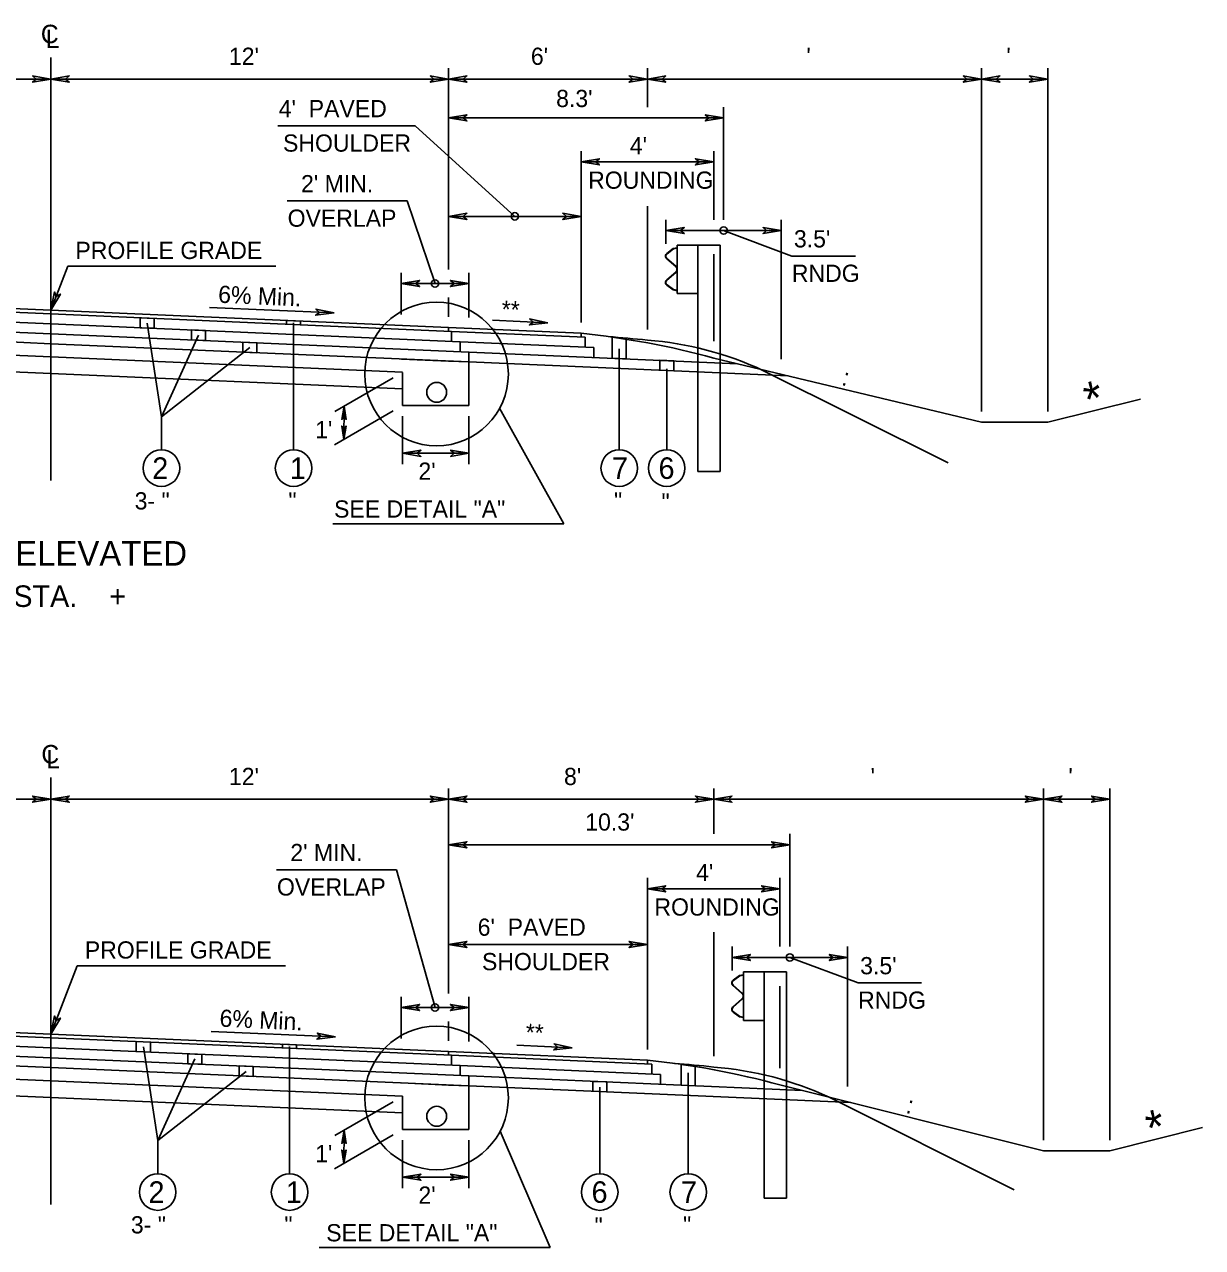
# Model space of a CAD drawing. Extents: x -592 to 1199, y -590 to 416.
# Drawn here: x 1091.9 to 1187.7, y 108.9 to 208.3 of the extents above; entities that cross this region are included whole.
import ezdxf

# ---------------------------------------------------------------- set-up
doc = ezdxf.new("R2010")
doc.units = 0
doc.layers.add('1', color=7, linetype='Continuous')
doc.layers.add('Des_ Drain_ Ftrs', color=7, linetype='Continuous')

msp = doc.modelspace()

# ---------------------------------------------------------------- linework, layer by layer
at = {"layer": '1'}
for p, q in [((1094.032, 171.242), (1094.032, 205.648)), ((1094.032, 203.888), (1061.702, 203.888)), ((1094.032, 203.888), (1126.361, 203.888)), ((1126.361, 188.391), (1126.361, 204.768)), ((1126.361, 203.888), (1142.526, 203.888)), ((1142.526, 201.606), (1142.526, 204.768)), ((1142.526, 203.888), (1169.691, 203.888)), ((1169.691, 176.868), (1169.691, 204.768)), ((1169.691, 203.888), (1175.079, 203.888)), ((1175.079, 176.868), (1175.079, 204.768)), ((1148.721, 192.45), (1148.721, 201.606)), ((1123.632, 200.084), (1112.491, 200.084)), ((1131.749, 192.725), (1123.635, 200.082)), ((1126.36, 200.726), (1148.721, 200.726)), ((1137.137, 184.095), (1137.137, 198.032)), ((1147.914, 192.45), (1147.914, 198.032)), ((1137.137, 197.152), (1147.914, 197.152)), ((1113.242, 193.979), (1123.006, 193.979)), ((1125.26, 187.263), (1123.006, 193.979)), ((1142.526, 183.54), (1142.526, 193.551)), ((1126.361, 192.725), (1137.137, 192.725)), ((1144.029, 190.499), (1144.029, 192.45)), ((1153.413, 181.106), (1153.413, 192.45)), ((1144.029, 191.57), (1153.413, 191.57)), ((1148.721, 191.57), (1154.279, 189.498)), ((1144.627, 190.102), (1144.11, 189.713)), ((1144.639, 190.074), (1144.128, 189.689)), ((1144.942, 190.158), (1144.627, 190.102)), ((1144.942, 190.127), (1144.639, 190.074)), ((1144.942, 190.386), (1144.942, 186.454)), ((1144.942, 190.386), (1146.627, 190.386)), ((1146.627, 190.386), (1146.627, 171.989)), ((1148.452, 190.386), (1146.627, 190.386)), ((1148.452, 190.386), (1148.452, 171.989)), ((1144.095, 189.281), (1144.827, 188.645)), ((1144.114, 189.303), (1144.846, 188.668)), ((1147.914, 182.572), (1147.914, 189.647)), ((1154.279, 189.498), (1159.434, 189.498)), ((1094.032, 185.1), (1095.408, 188.672)), ((1112.327, 188.672), (1095.408, 188.672)), ((1122.517, 184.734), (1122.517, 188.143)), ((1128.003, 184.494), (1128.003, 188.143)), ((1144.827, 188.195), (1144.095, 187.559)), ((1144.846, 188.172), (1144.114, 187.537)), ((1144.913, 188.458), (1144.913, 188.382)), ((1144.942, 188.458), (1144.942, 188.382)), ((1122.517, 187.263), (1128.003, 187.263)), ((1144.11, 187.127), (1144.627, 186.738)), ((1144.128, 187.151), (1144.639, 186.766)), ((1094.032, 184.799), (1061.356, 186.226)), ((1094.032, 185.099), (1061.696, 186.511)), ((1126.361, 184.566), (1126.361, 186.134)), ((1144.627, 186.738), (1144.942, 186.682)), ((1144.639, 186.766), (1144.942, 186.712)), ((1144.942, 186.454), (1146.627, 186.454)), ((1094.032, 183.99), (1060.434, 185.457)), ((1126.366, 183.686), (1094.032, 185.1)), ((1106.935, 185.31), (1117.047, 184.868)), ((1094.032, 183.181), (1059.511, 184.688)), ((1126.601, 183.377), (1094.032, 184.799)), ((1127.304, 182.537), (1094.032, 183.99)), ((1101.851, 184.052), (1103.015, 176.426)), ((1113.759, 184.06), (1113.759, 173.742)), ((1134.427, 184.081), (1129.933, 184.277)), ((1094.032, 182.372), (1059.511, 183.879)), ((1128.008, 181.697), (1094.032, 183.181)), ((1106.027, 183.069), (1103.015, 176.426)), ((1137.137, 183.215), (1126.366, 183.686)), ((1126.366, 183.686), (1126.366, 183.386)), ((1126.601, 183.377), (1126.601, 182.568)), ((1137.471, 182.902), (1126.603, 183.377)), ((1137.137, 183.215), (1137.137, 182.915)), ((1094.032, 181.293), (1064.9, 182.565)), ((1128.008, 180.888), (1094.032, 182.372)), ((1110.202, 182.055), (1103.015, 176.426)), ((1127.304, 182.537), (1127.304, 181.728)), ((1138.166, 182.062), (1127.314, 182.536)), ((1137.471, 182.902), (1137.471, 182.093)), ((1138.166, 182.062), (1138.166, 181.252)), ((1140.235, 181.948), (1140.235, 173.742)), ((1144.029, 182.439), (1144.029, 182.439)), ((1094.032, 179.945), (1064.9, 181.217)), ((1122.619, 180.045), (1094.032, 181.293)), ((1126.361, 180.96), (1122.522, 181.128)), ((1128.008, 180.888), (1126.351, 180.961)), ((1128.008, 181.697), (1128.008, 180.888)), ((1149.853, 180.742), (1128.025, 181.695)), ((1147.914, 181.206), (1169.691, 175.988)), ((1122.619, 177.35), (1122.619, 180.044)), ((1122.619, 180.044), (1122.619, 180.044)), ((1128.008, 177.35), (1128.008, 180.888)), ((1153.971, 179.755), (1128.008, 180.888)), ((1144.095, 180.34), (1144.095, 173.742)), ((1151.914, 180.206), (1166.965, 172.68)), ((1122.619, 178.697), (1094.032, 179.945)), ((1121.857, 179.604), (1117.1, 176.858)), ((1117.862, 177.298), (1117.841, 174.592)), ((1122.619, 177.35), (1128.008, 177.35)), ((1130.513, 177.123), (1135.74, 167.732)), ((1182.615, 177.872), (1175.079, 175.988)), ((1103.015, 176.426), (1103.015, 173.742)), ((1121.857, 176.91), (1117.085, 174.155)), ((1122.619, 176.47), (1122.619, 172.584)), ((1128.008, 176.47), (1128.008, 172.584)), ((1169.691, 175.988), (1175.08, 175.988)), ((1122.619, 173.464), (1128.008, 173.464)), ((1148.452, 171.989), (1146.627, 171.989)), ((1116.954, 167.732), (1135.74, 167.732)), ((1094.032, 112.392), (1094.032, 147.103)), ((1126.361, 129.541), (1126.361, 146.223)), ((1147.914, 142.521), (1147.914, 146.223)), ((1174.737, 117.641), (1174.737, 146.223)), ((1180.125, 117.641), (1180.125, 146.223)), ((1094.032, 145.343), (1061.702, 145.343)), ((1094.032, 145.343), (1126.361, 145.343)), ((1126.361, 145.343), (1147.914, 145.343)), ((1147.914, 145.343), (1174.737, 145.343)), ((1174.737, 145.343), (1180.125, 145.343)), ((1154.109, 133.365), (1154.109, 142.521)), ((1126.359, 141.641), (1154.109, 141.641)), ((1112.373, 139.613), (1122.137, 139.613)), ((1125.26, 128.413), (1122.137, 139.613)), ((1142.526, 125.011), (1142.526, 138.947)), ((1153.302, 133.365), (1153.302, 138.947)), ((1142.526, 138.067), (1153.302, 138.067)), ((1147.914, 124.455), (1147.914, 134.548)), ((1126.361, 133.543), (1142.526, 133.543)), ((1149.417, 131.414), (1149.417, 133.365)), ((1158.801, 122.001), (1158.801, 133.365)), ((1149.417, 132.485), (1158.801, 132.485)), ((1154.109, 132.485), (1159.666, 130.414)), ((1094.032, 126.25), (1096.173, 131.806)), ((1113.091, 131.806), (1096.173, 131.806)), ((1150.33, 131.301), (1150.33, 127.369)), ((1150.33, 131.301), (1152.015, 131.301)), ((1152.015, 131.301), (1152.015, 112.904)), ((1153.84, 131.301), (1152.015, 131.301)), ((1153.84, 131.301), (1153.84, 112.904)), ((1150.015, 131.017), (1149.498, 130.628)), ((1150.027, 130.989), (1149.516, 130.604)), ((1150.33, 131.073), (1150.015, 131.017)), ((1150.33, 131.042), (1150.027, 130.989)), ((1159.666, 130.414), (1164.821, 130.414)), ((1122.517, 125.884), (1122.517, 129.293)), ((1128.003, 125.645), (1128.003, 129.293)), ((1149.483, 130.196), (1150.214, 129.56)), ((1149.502, 130.218), (1150.234, 129.583)), ((1150.3, 129.373), (1150.3, 129.297)), ((1150.33, 129.373), (1150.33, 129.297)), ((1153.302, 123.488), (1153.302, 130.135)), ((1122.517, 128.413), (1128.003, 128.413)), ((1150.214, 129.11), (1149.483, 128.474)), ((1150.234, 129.087), (1149.502, 128.452)), ((1094.032, 125.949), (1061.356, 127.376)), ((1094.032, 126.249), (1061.696, 127.661)), ((1126.361, 125.716), (1126.361, 127.285)), ((1149.498, 128.042), (1150.015, 127.653)), ((1149.516, 128.066), (1150.027, 127.681)), ((1150.015, 127.653), (1150.33, 127.597)), ((1150.027, 127.681), (1150.33, 127.627)), ((1150.33, 127.369), (1152.015, 127.369)), ((1094.032, 125.14), (1060.434, 126.607)), ((1107.047, 126.461), (1117.16, 126.019)), ((1094.032, 124.331), (1059.511, 125.838)), ((1126.366, 124.836), (1094.032, 126.25)), ((1126.601, 124.527), (1094.032, 125.949)), ((1136.41, 125.145), (1131.916, 125.341)), ((1094.032, 123.522), (1059.511, 125.029)), ((1127.304, 123.688), (1094.032, 125.14)), ((1128.008, 122.848), (1094.032, 124.331)), ((1101.546, 125.218), (1102.71, 117.592)), ((1113.432, 125.23), (1113.432, 114.893)), ((1142.526, 124.131), (1126.366, 124.836)), ((1126.366, 124.836), (1126.366, 124.536)), ((1142.888, 123.815), (1126.601, 124.527)), ((1126.601, 124.527), (1126.601, 123.718)), ((1094.032, 122.443), (1064.9, 123.715)), ((1128.008, 122.039), (1094.032, 123.522)), ((1105.722, 124.234), (1102.71, 117.592)), ((1143.583, 122.977), (1127.304, 123.688)), ((1127.304, 123.688), (1127.304, 122.878)), ((1142.526, 124.131), (1142.526, 123.83)), ((1142.888, 123.815), (1142.888, 123.007)), ((1149.417, 123.354), (1149.417, 123.354)), ((1094.032, 121.095), (1064.9, 122.367)), ((1122.619, 121.195), (1094.032, 122.443)), ((1109.897, 123.221), (1102.71, 117.592)), ((1128.008, 122.848), (1128.008, 122.039)), ((1155.135, 121.663), (1128.008, 122.848)), ((1143.583, 122.977), (1143.583, 122.168)), ((1145.846, 123.095), (1145.846, 114.893)), ((1126.361, 122.111), (1122.522, 122.278)), ((1128.008, 122.039), (1126.362, 122.111)), ((1128.008, 118.501), (1128.008, 122.039)), ((1159.055, 120.683), (1128.008, 122.039)), ((1138.65, 121.947), (1138.65, 114.893)), ((1153.302, 122.121), (1174.737, 116.761)), ((1122.619, 119.847), (1094.032, 121.095)), ((1121.857, 120.755), (1117.1, 118.008)), ((1122.619, 118.501), (1122.619, 121.195)), ((1122.619, 121.195), (1122.619, 121.195)), ((1157.301, 121.121), (1172.352, 113.595)), ((1117.862, 118.448), (1117.841, 115.742)), ((1122.619, 118.501), (1128.008, 118.501)), ((1130.561, 118.365), (1134.616, 108.9)), ((1187.66, 118.645), (1180.125, 116.761)), ((1102.71, 117.592), (1102.71, 114.893)), ((1121.857, 118.061), (1117.085, 115.305)), ((1122.619, 117.621), (1122.619, 113.735)), ((1128.008, 117.621), (1128.008, 113.735)), ((1174.737, 116.761), (1180.125, 116.761)), ((1122.619, 114.615), (1128.008, 114.615)), ((1153.84, 112.904), (1152.015, 112.904)), ((1115.83, 108.9), (1134.616, 108.9))]:
    msp.add_line(p, q, dxfattribs=at)
for points in [[(1101.278, 184.483), (1102.425, 184.433), (1102.425, 183.624), (1101.278, 183.674)], [(1113.185, 184.262), (1114.332, 184.212), (1114.332, 183.913), (1113.185, 183.963)], [(1105.454, 183.491), (1106.6, 183.441), (1106.6, 182.632), (1105.454, 182.682)], [(1109.629, 182.5), (1110.776, 182.45), (1110.776, 181.641), (1109.629, 181.691)], [(1139.662, 182.907), (1140.808, 182.735), (1140.808, 181.137), (1139.662, 181.187)], [(1143.526, 181.022), (1144.673, 180.972), (1144.673, 180.165), (1143.526, 180.215)], [(1100.973, 125.646), (1102.12, 125.596), (1102.12, 124.787), (1100.973, 124.837)], [(1112.858, 125.427), (1114.005, 125.377), (1114.005, 125.077), (1112.858, 125.127)], [(1105.149, 124.655), (1106.295, 124.605), (1106.295, 123.796), (1105.149, 123.846)], [(1109.324, 123.663), (1110.471, 123.613), (1110.471, 122.804), (1109.324, 122.854)], [(1145.273, 123.79), (1146.42, 123.614), (1146.42, 122.044), (1145.273, 122.094)], [(1138.077, 122.408), (1139.223, 122.358), (1139.223, 121.549), (1138.077, 121.599)]]:
    msp.add_lwpolyline(points, close=True, dxfattribs=at)
for centre, radius in [((1131.749, 192.725), 0.3), ((1148.722, 191.57), 0.3), ((1125.26, 187.263), 0.3), ((1125.382, 179.908), 5.838), ((1125.394, 178.421), 0.808), ((1103.015, 172.257), 1.485), ((1113.759, 172.257), 1.485), ((1140.235, 172.257), 1.485), ((1144.095, 172.257), 1.485), ((1154.109, 132.485), 0.3), ((1125.26, 128.413), 0.3), ((1125.382, 121.059), 5.838), ((1125.394, 119.571), 0.808), ((1102.71, 113.407), 1.485), ((1113.432, 113.407), 1.485), ((1138.65, 113.407), 1.485), ((1145.846, 113.407), 1.485)]:
    msp.add_circle(centre, radius, dxfattribs=at)
for centre, radius, start, end in [((1144.278, 189.491), 0.278, 126.97989, 229.02099), ((1144.278, 189.491), 0.249, 126.97989, 229.02099), ((1144.664, 188.458), 0.249, 0, 49.03649), ((1144.664, 188.382), 0.249, 310.96352, 0), ((1144.664, 188.458), 0.278, 0, 49.03649), ((1144.664, 188.382), 0.278, 310.96352, 0), ((1144.278, 187.349), 0.278, 130.97902, 233.02011), ((1144.278, 187.349), 0.249, 130.97902, 233.02011), ((1130.253, 116.381), 67.188, 74.76019, 84.11876), ((1131.707, 81.996), 101.244, 83.86333, 85.67746), ((1140.407, 155.374), 27.368, 65.13739, 85.55132), ((1149.665, 130.406), 0.278, 126.97989, 229.02099), ((1149.665, 130.406), 0.249, 126.97989, 229.02099), ((1150.052, 129.373), 0.249, 0, 49.03649), ((1150.052, 129.297), 0.249, 310.96352, 0), ((1150.052, 129.373), 0.278, 0, 49.03649), ((1150.052, 129.297), 0.278, 310.96352, 0), ((1149.665, 128.264), 0.278, 130.97902, 233.02011), ((1149.665, 128.264), 0.249, 130.97902, 233.02011), ((1135.641, 57.296), 67.188, 74.76019, 84.11876), ((1137.094, 22.911), 101.244, 83.86333, 85.67746), ((1145.794, 96.289), 27.368, 65.13739, 85.55132)]:
    msp.add_arc(centre, radius, start, end, dxfattribs=at)
at = {"layer": 'Des_ Drain_ Ftrs'}
for points in [[(1094.032, 203.888), (1092.543, 203.64), (1092.838, 203.888), (1092.543, 204.136)], [(1094.032, 203.888), (1095.52, 203.64), (1095.225, 203.888), (1095.52, 204.136)], [(1126.361, 203.888), (1124.873, 203.64), (1125.168, 203.888), (1124.873, 204.136)], [(1126.361, 203.888), (1127.849, 203.64), (1127.554, 203.888), (1127.849, 204.136)], [(1142.526, 203.888), (1141.037, 203.64), (1141.332, 203.888), (1141.037, 204.136)], [(1142.526, 203.888), (1144.014, 203.64), (1143.719, 203.888), (1144.014, 204.136)], [(1169.691, 203.888), (1168.203, 203.64), (1168.498, 203.888), (1168.203, 204.136)], [(1169.691, 203.888), (1171.18, 203.64), (1170.885, 203.888), (1171.18, 204.136)], [(1175.079, 203.888), (1173.591, 203.64), (1173.886, 203.888), (1173.591, 204.136)], [(1126.36, 200.726), (1127.848, 200.478), (1127.553, 200.726), (1127.848, 200.974)], [(1148.721, 200.726), (1147.233, 200.478), (1147.528, 200.726), (1147.233, 200.974)], [(1137.137, 197.152), (1138.626, 196.904), (1138.331, 197.152), (1138.626, 197.4)], [(1147.914, 197.152), (1146.426, 196.904), (1146.721, 197.152), (1146.426, 197.4)], [(1126.361, 192.725), (1127.849, 192.477), (1127.554, 192.725), (1127.849, 192.974)], [(1137.137, 192.725), (1135.649, 192.477), (1135.944, 192.725), (1135.649, 192.974)], [(1144.029, 191.57), (1145.518, 191.322), (1145.223, 191.57), (1145.518, 191.818)], [(1153.413, 191.57), (1151.925, 191.322), (1152.22, 191.57), (1151.925, 191.818)], [(1122.517, 187.263), (1124.005, 187.014), (1123.71, 187.263), (1124.005, 187.511)], [(1128.003, 187.263), (1126.515, 187.014), (1126.81, 187.263), (1126.515, 187.511)], [(1094.032, 185.1), (1094.796, 186.4), (1094.459, 186.214), (1094.333, 186.578)], [(1117.047, 184.868), (1115.549, 184.684), (1115.855, 184.92), (1115.571, 185.181)], [(1134.427, 184.081), (1132.929, 183.896), (1133.234, 184.132), (1132.95, 184.393)], [(1117.862, 177.298), (1117.673, 176.214), (1117.856, 176.428), (1118.035, 176.212)], [(1117.841, 174.592), (1117.669, 175.678), (1117.848, 175.462), (1118.031, 175.675)], [(1122.619, 173.464), (1124.108, 173.216), (1123.813, 173.464), (1124.108, 173.713)], [(1128.008, 173.464), (1126.52, 173.216), (1126.815, 173.464), (1126.52, 173.713)], [(1094.032, 145.343), (1092.543, 145.095), (1092.838, 145.343), (1092.543, 145.592)], [(1094.032, 145.343), (1095.52, 145.095), (1095.225, 145.343), (1095.52, 145.592)], [(1126.361, 145.343), (1124.873, 145.095), (1125.168, 145.343), (1124.873, 145.592)], [(1126.361, 145.343), (1127.849, 145.095), (1127.554, 145.343), (1127.849, 145.592)], [(1147.914, 145.343), (1146.425, 145.095), (1146.72, 145.343), (1146.425, 145.592)], [(1147.914, 145.343), (1149.402, 145.095), (1149.107, 145.343), (1149.402, 145.592)], [(1174.737, 145.343), (1173.249, 145.095), (1173.544, 145.343), (1173.249, 145.592)], [(1174.737, 145.343), (1176.225, 145.095), (1175.93, 145.343), (1176.225, 145.592)], [(1180.125, 145.343), (1178.637, 145.095), (1178.932, 145.343), (1178.637, 145.592)], [(1126.359, 141.641), (1127.847, 141.393), (1127.552, 141.641), (1127.847, 141.889)], [(1154.109, 141.641), (1152.621, 141.393), (1152.916, 141.641), (1152.621, 141.889)], [(1142.526, 138.067), (1144.014, 137.819), (1143.719, 138.067), (1144.014, 138.316)], [(1153.302, 138.067), (1151.814, 137.819), (1152.109, 138.067), (1151.814, 138.316)], [(1126.361, 133.543), (1127.849, 133.294), (1127.554, 133.543), (1127.849, 133.791)], [(1142.526, 133.543), (1141.037, 133.294), (1141.332, 133.543), (1141.037, 133.791)], [(1149.417, 132.485), (1150.905, 132.237), (1150.61, 132.485), (1150.905, 132.733)], [(1158.801, 132.485), (1157.313, 132.237), (1157.608, 132.485), (1157.313, 132.733)], [(1122.517, 128.413), (1124.005, 128.165), (1123.71, 128.413), (1124.005, 128.661)], [(1128.003, 128.413), (1126.515, 128.165), (1126.81, 128.413), (1126.515, 128.661)], [(1094.032, 126.25), (1094.796, 127.551), (1094.459, 127.364), (1094.333, 127.728)], [(1117.16, 126.019), (1115.662, 125.835), (1115.967, 126.071), (1115.684, 126.332)], [(1136.41, 125.145), (1134.912, 124.96), (1135.218, 125.196), (1134.934, 125.456)], [(1117.862, 118.448), (1117.673, 117.365), (1117.856, 117.578), (1118.035, 117.362)], [(1117.841, 115.742), (1117.669, 116.828), (1117.848, 116.612), (1118.031, 116.825)], [(1122.619, 114.615), (1124.108, 114.366), (1123.813, 114.615), (1124.108, 114.863)], [(1128.008, 114.615), (1126.52, 114.366), (1126.815, 114.615), (1126.52, 114.863)]]:
    msp.add_lwpolyline(points, close=True, dxfattribs=at)

# ---------------------------------------------------------------- texts
at = {"layer": '1'}
for s, height, p in [("12'", 1.4, (1108.503, 205.039)), ("6'", 1.4, (1133.053, 205.039)), ("  '", 1.4, (1154.412, 205.039)), (" '", 1.4, (1171.19, 205.039)), ("8.3'", 1.4, (1135.104, 201.607)), ("4'  PAVED", 1.4, (1112.551, 200.784)), ('SHOULDER', 1.4, (1112.9, 197.984)), ("4'", 1.4, (1141.097, 197.768)), ("2' MIN.", 1.4, (1114.364, 194.679)), ('ROUNDING', 1.4, (1137.708, 194.968)), ('OVERLAP', 1.4, (1113.275, 191.879)), ("3.5'", 1.4, (1154.438, 190.198)), ('PROFILE GRADE', 1.4, (1096.021, 189.257)), ('RNDG', 1.4, (1154.268, 187.398)), ('2', 1.75, (1102.268, 171.382)), ('1', 1.75, (1113.457, 171.382)), ('7', 1.75, (1139.644, 171.382)), ('6', 1.75, (1143.43, 171.382)), ("2'", 1.4, (1123.91, 171.313)), ('3- "', 1.4, (1100.836, 168.897)), (' "', 1.4, (1112.815, 168.897)), (' "', 1.4, (1139.291, 168.897)), (' "', 1.4, (1143.151, 168.801)), ('SEE DETAIL "A"', 1.4, (1117.052, 168.235)), ('SUPERELEVATED', 2, (1081.912, 164.329)), ('STA.    +      TO STA.    +     ', 1.75, (1074.002, 160.973)), ("12'", 1.4, (1108.503, 146.494)), ("8'", 1.4, (1135.747, 146.494)), ("  '", 1.4, (1159.629, 146.494)), (" '", 1.4, (1176.236, 146.494)), ("10.3'", 1.4, (1137.472, 142.792)), ("2' MIN.", 1.4, (1113.495, 140.313)), ("4'", 1.4, (1146.485, 138.683)), ('OVERLAP', 1.4, (1112.406, 137.513)), ('ROUNDING', 1.4, (1143.096, 135.883)), ("6'  PAVED", 1.4, (1128.727, 134.243)), ('PROFILE GRADE', 1.4, (1096.785, 132.391)), ('SHOULDER', 1.4, (1129.076, 131.443)), ("3.5'", 1.4, (1159.825, 131.113)), ('RNDG', 1.4, (1159.656, 128.313)), ('2', 1.75, (1101.963, 112.532)), ('1', 1.75, (1113.13, 112.532)), ("2'", 1.4, (1123.91, 112.463)), ('6', 1.75, (1137.985, 112.532)), ('7', 1.75, (1145.255, 112.532)), ('3- "', 1.4, (1100.531, 110.048)), (' "', 1.4, (1112.488, 110.048)), (' "', 1.4, (1144.902, 110.048)), ('SEE DETAIL "A"', 1.4, (1116.414, 109.403)), (' "', 1.4, (1137.706, 109.951))]:
    msp.add_text(s, height=height, dxfattribs=at).set_placement(p)
for s, height, rotation, p in [('6% Min.', 1.4, 357.37268, (1107.603, 185.708)), ('**', 1.4, 357.21655, (1130.641, 184.486)), (' : ', 1.4, 345.77179, (1157.744, 179.152)), ('*', 2.8, 12.84793, (1178.395, 176.393)), ("1'", 1.4, 0.14377, (1115.514, 174.681)), ('6% Min.', 1.4, 357.37309, (1107.716, 126.859)), ('**', 1.4, 357.2167, (1132.596, 125.706)), (' : ', 1.4, 345.77179, (1162.97, 119.994)), ('*', 2.8, 12.84793, (1183.44, 117.167)), ("1'", 1.4, 0.14377, (1115.514, 115.831))]:
    msp.add_text(s, height=height, rotation=rotation, dxfattribs=at).set_placement(p)
at = {"layer": 'Des_ Drain_ Ftrs'}
for s, p in [('C', (1093.209, 206.8)), ('L', (1093.602, 206.403)), ('C', (1093.251, 148.253)), ('L', (1093.645, 147.855))]:
    msp.add_text(s, height=1.5, dxfattribs=at).set_placement(p)

doc.saveas('drawing.dxf')
